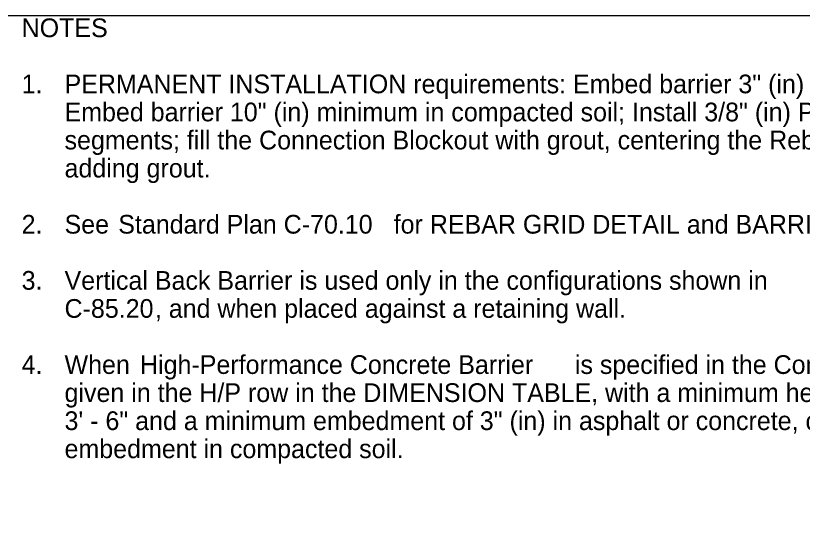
# Model space of a CAD drawing. Extents: x 99862 to 103680, y 99470 to 102076.
# Drawn here: x 101837 to 102678, y 101514 to 102076 of the extents above; entities that cross this region are included whole.
import ezdxf

# ---------------------------------------------------------------- set-up
doc = ezdxf.new("R2010")
doc.units = 0
doc.layers.add('Level 1', color=7, linetype='Continuous')
doc.layers.add('Level 20', color=7, linetype='Continuous')

msp = doc.modelspace()

# ---------------------------------------------------------------- linework, layer by layer
at = {"layer": 'Level 1'}
msp.add_lwpolyline([(99862, 99999.5), (103151, 99999.5), (103151, 102075.5), (99862, 102075.5)], close=True, dxfattribs=at)

# ---------------------------------------------------------------- texts
at = {"layer": 'Level 20'}
for s, p in [('NOTES', (101843.04, 102052.63)), ('1.', (101843.04, 101992.63)), ('PERMANENT INSTALLATION requirements: Embed barrier 3" (in) minimum in asphalt or concrete;', (101888.95, 101992.63)), ('Embed barrier 10" (in) minimum in compacted soil; Install 3/8" (in) Premolded Joint Filler between ', (101888.95, 101962.63)), ('segments; fill the Connection Blockout with grout, centering the Rebar Grid in the blockout before ', (101888.95, 101932.63)), ('adding grout.', (101888.95, 101902.63)), ('2.', (101843.04, 101842.63)), ('See ', (101888.95, 101842.63)), ('Standard Plan C-70.10', (101946.42, 101842.63)), ('for REBAR GRID DETAIL and BARRIER CONNECTION DETAIL.', (102241.03, 101842.63)), ('3.', (101843.04, 101782.63)), ('Vertical Back Barrier is used only in the configurations shown in ', (101888.95, 101782.63)), (', and when placed against a retaining wall.', (101985.6, 101752.63)), ('C-85.20', (101888.95, 101752.63)), ('4.', (101843.04, 101692.63)), ('When ', (101888.95, 101692.63)), ('High-Performance Concrete Barrier', (101969.68, 101692.63)), ('is specified in the Contract, use the dimensions ', (102434.88, 101692.63)), ('given in the H/P row in the DIMENSION TABLE, with a minimum height above roadway of ', (101888.95, 101662.63)), ('3\' - 6" and a minimum embedment of 3" (in) in asphalt or concrete, or 10" (in) minimum ', (101888.95, 101632.63)), ('embedment in compacted soil.', (101888.95, 101602.63))]:
    msp.add_text(s, height=20, dxfattribs=at).set_placement(p)

doc.saveas('drawing.dxf')
